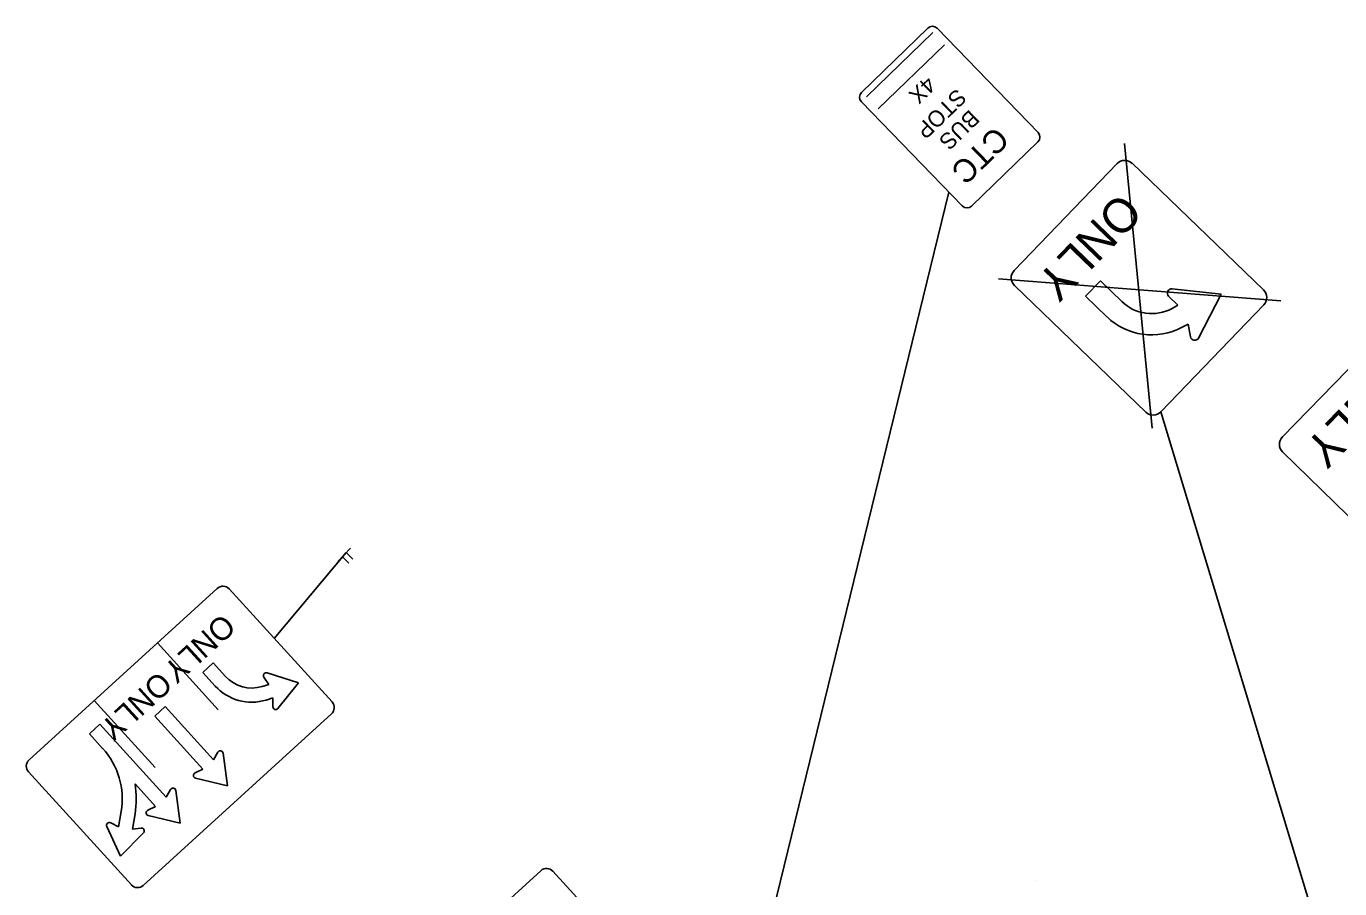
# Model space of a CAD drawing. Extents: x 1479394 to 1483660, y 379804 to 384342.
# Drawn here: x 1479411.1 to 1479604.6, y 379995.2 to 380122.2 of the extents above; entities that cross this region are included whole.
import ezdxf

# ---------------------------------------------------------------- set-up
doc = ezdxf.new("R2010")
doc.units = 0
for name, color, linetype in [('PM_P_Cells', 7, 'Continuous'), ('RD_P_Text', 7, 'Continuous'), ('SC_Scratch15', 7, 'Continuous'), ('SH_Text', 7, 'Continuous')]:
    doc.layers.add(name, color=color, linetype=linetype)

msp = doc.modelspace()

# ---------------------------------------------------------------- linework, layer by layer
at = {"layer": 'PM_P_Cells'}
msp.add_line((1479559.72, 379996.41), (1479559.72, 379996.41), dxfattribs=at)
at = {"layer": 'RD_P_Text'}
for p, q in [((1479456.97, 380043.43), (1479458.85, 380045.39)), ((1479447.59, 380032.09), (1479458.19, 380044.71)), ((1479457.63, 380044.12), (1479458.61, 380043.18)), ((1479457.91, 380044.41), (1479457.91, 380044.41)), ((1479457.91, 380044.41), (1479457.91, 380044.41)), ((1479458.19, 380044.71), (1479459.17, 380043.76)), ((1479439.37, 380021.55), (1479430.39, 380031.41)), ((1479437.08, 380027.08), (1479438.62, 380028.48)), ((1479438.62, 380028.48), (1479440.45, 380026.48)), ((1479438.91, 380025.07), (1479437.08, 380027.08)), ((1479446.82, 380025.31), (1479446.09, 380026.37)), ((1479446.56, 380027), (1479451.17, 380025.54)), ((1479445.81, 380025), (1479446.82, 380025.31)), ((1479451.17, 380025.54), (1479448.15, 380021.76)), ((1479430.05, 380013.06), (1479421.07, 380022.92)), ((1479431.54, 380022.03), (1479430, 380020.62)), ((1479438.65, 380014.22), (1479431.54, 380022.03)), ((1479447.42, 380023.31), (1479446.41, 380023.01)), ((1479447.41, 380022.02), (1479447.42, 380023.31)), ((1479430, 380020.62), (1479437.11, 380012.82)), ((1479421.91, 380019.45), (1479420.37, 380018.05)), ((1479431.68, 380008.72), (1479421.91, 380019.45)), ((1479420.37, 380018.05), (1479422.33, 380015.89)), ((1479439.3, 380015.33), (1479438.65, 380014.22)), ((1479440.73, 380010.39), (1479440.07, 380015.18)), ((1479437.11, 380012.82), (1479435.94, 380012.27)), ((1479427.11, 380010.65), (1479430.14, 380007.32)), ((1479436.02, 380011.49), (1479440.73, 380010.39)), ((1479432.33, 380009.83), (1479431.68, 380008.72)), ((1479433.76, 380004.89), (1479433.11, 380009.68)), ((1479425.05, 380006.6), (1479424.67, 380004.34)), ((1479430.14, 380007.32), (1479428.98, 380006.77)), ((1479424.67, 380004.34), (1479423.52, 380004.92)), ((1479426.72, 380003.99), (1479427.11, 380006.25)), ((1479429.06, 380005.99), (1479433.76, 380004.89)), ((1479422.95, 380004.38), (1479424.98, 379999.99)), ((1479424.98, 379999.99), (1479428.35, 380003.46)), ((1479428, 380004.16), (1479426.72, 380003.99))]:
    msp.add_line(p, q, dxfattribs=at)
for points in [[(1479439.21, 380039.44), (1479411.49, 380014.19)], [(1479456.13, 380022.72), (1479440.97, 380039.36)], [(1479428.32, 379995.7), (1479456.04, 380020.96)], [(1479411.4, 380012.42), (1479426.56, 379995.79)]]:
    msp.add_lwpolyline(points, dxfattribs=at)
for centre, radius, start, end in [((1479440.05, 380038.52), 1.25, 42.331, 132.331), ((1479444.3, 380029.98), 5.21, 222.331, 286.8483), ((1479446.44, 380026.61), 0.417, 72.332, 214.2101), ((1479444.3, 380029.98), 7.29, 222.331, 286.8483), ((1479447.83, 380022.02), 0.417, 179.4864, 321.3645), ((1479455.2, 380021.88), 1.25, 312.331, 42.331), ((1479414.17, 380008.46), 11.04, 350.3167, 42.331), ((1479439.66, 380015.12), 0.417, 7.8147, 149.6928), ((1479412.33, 380013.26), 1.25, 132.331, 222.331), ((1479414.17, 380008.46), 13.12, 350.3167, 9.6054), ((1479436.12, 380011.9), 0.417, 114.9691, 256.8472), ((1479432.69, 380009.62), 0.417, 7.8147, 149.6928), ((1479429.15, 380006.39), 0.417, 114.9691, 256.8472), ((1479423.33, 380004.55), 0.417, 62.9548, 204.8329), ((1479428.05, 380003.75), 0.417, 315.8004, 97.6785), ((1479427.48, 379996.63), 1.25, 222.331, 312.331)]:
    msp.add_arc(centre, radius, start, end, dxfattribs=at)
at = {"layer": 'SC_Scratch15'}
for p, q in [((1479576.95, 380063.02), (1479572.9, 380104.99)), ((1479554.31, 380085.06), (1479595.9, 380081.8)), ((1479569.32, 380084.72), (1479567.15, 380082.47)), ((1479572.47, 380081.69), (1479569.32, 380084.72)), ((1479567.15, 380082.47), (1479570.3, 380079.43)), ((1479579.38, 380082.49), (1479580.76, 380081.14)), ((1479587.11, 380082.78), (1479579.88, 380083.56)), ((1479583.77, 380076.32), (1479587.11, 380082.78)), ((1479580.76, 380081.14), (1479579.88, 380080.67)), ((1479581.36, 380077.91), (1479582.24, 380078.38)), ((1479582.24, 380078.38), (1479582.6, 380076.48)), ((1479578.23, 380065.44), (1479613.9, 379947.6))]:
    msp.add_line(p, q, dxfattribs=at)
for points in [[(1479571.79, 380102.01), (1479556.62, 380086.24)], [(1479593.36, 380083.41), (1479574, 380102.05)], [(1479556.66, 380084.03), (1479576.03, 380065.4)], [(1479578.23, 380065.44), (1479593.4, 380081.2)], [(1479611.41, 380077.42), (1479596.14, 380061.76)], [(1479596.17, 380059.55), (1479615.41, 380040.79)], [(1479486.89, 379997.87), (1479459.17, 379972.62)], [(1479503.81, 379981.16), (1479488.66, 379997.79)]]:
    msp.add_lwpolyline(points, dxfattribs=at)
for centre, radius, start, end in [((1479572.91, 380100.92), 1.56, 46.1, 136.1), ((1479557.74, 380085.16), 1.56, 136.1, 226.1), ((1479579.81, 380082.93), 0.625, 83.8543, 225.626), ((1479592.28, 380082.29), 1.56, 316.1, 46.1), ((1479576.88, 380086.26), 6.35, 226.1, 298.2387), ((1479576.88, 380086.26), 9.48, 226.1, 298.2425), ((1479583.22, 380076.6), 0.625, 190.8936, 332.6653), ((1479577.11, 380066.52), 1.56, 226.1, 316.1), ((1479597.26, 380060.67), 1.56, 135.7261, 225.7261), ((1479487.74, 379996.95), 1.25, 42.331, 132.331)]:
    msp.add_arc(centre, radius, start, end, dxfattribs=at)
at = {"layer": 'SH_Text'}
for p, q in [((1479534.86, 380111.85), (1479544.62, 380121.31)), ((1479536.59, 380110.05), (1479546.36, 380119.52)), ((1479547.02, 380097.79), (1479521.11, 379991.94))]:
    msp.add_line(p, q, dxfattribs=at)
for points in [[(1479534.13, 380112.49), (1479543.9, 380121.96)], [(1479545.27, 380121.93), (1479560.15, 380106.58)], [(1479548.98, 380095.77), (1479534.11, 380111.12)], [(1479560.12, 380105.21), (1479550.36, 380095.75)]]:
    msp.add_lwpolyline(points, dxfattribs=at)
for centre, start, end in [((1479544.57, 380121.26), 44.1, 134.1), ((1479534.81, 380111.79), 134.1, 224.1), ((1479559.45, 380105.91), 314.1, 44.1), ((1479549.68, 380096.44), 224.1, 314.1)]:
    msp.add_arc(centre, 0.972, start, end, dxfattribs=at)

# ---------------------------------------------------------------- texts
at = {"layer": 'RD_P_Text'}
for p in [(1479439.97, 380035.91), (1479430.65, 380027.42)]:
    msp.add_text('ONLY', height=3.333, rotation=222.331, dxfattribs=at).set_placement(p)
at = {"layer": 'SC_Scratch15'}
for rotation, p in [(226.1, (1479572.24, 380097.97)), (225.7261, (1479611.83, 380073.38))]:
    msp.add_text('ONLY', height=5, rotation=rotation, dxfattribs=at).set_placement(p)
at = {"layer": 'SH_Text'}
for s, height, p in [('4X', 2.38, (1479543.7, 380115.03)), ('STOP', 2.38, (1479548.16, 380113.2)), ('BUS', 2.38, (1479550.07, 380110.08)), ('CTC', 3.4, (1479553.8, 380107.67))]:
    msp.add_text(s, height=height, rotation=224.1, dxfattribs=at).set_placement(p)

doc.saveas('drawing.dxf')
